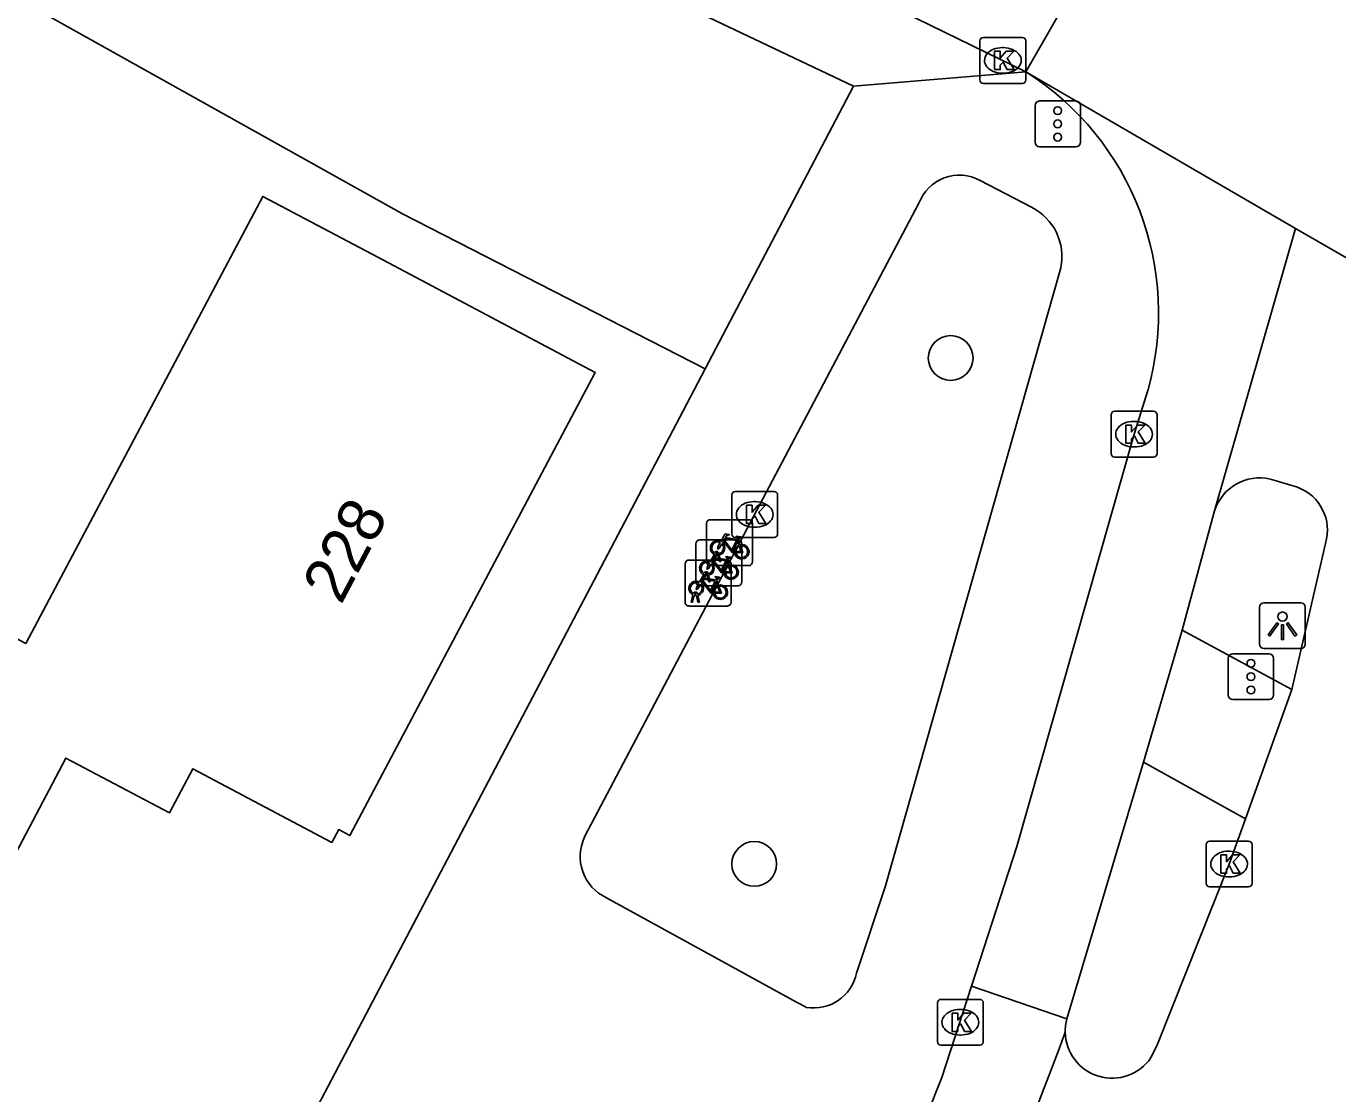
# Model space of a CAD drawing. Extents: x 160158 to 160921, y 381517 to 382041.
# Drawn here: x 160614.39 to 160643.01, y 381865.63 to 381888.94 of the extents above; entities that cross this region are included whole.
import ezdxf

# ---------------------------------------------------------------- set-up
doc = ezdxf.new("R2010")
doc.units = 0
for name, color, linetype in [('IMGEO_Boom', 7, 'Continuous'), ('IMGEO_Fietsenrek', 7, 'Continuous'), ('IMGEO_Fietspad_open', 7, 'Continuous'), ('IMGEO_Groenvoorziening', 7, 'Continuous'), ('IMGEO_Kolk', 7, 'Continuous'), ('IMGEO_Lichtpunt', 7, 'Continuous'), ('IMGEO_Pand', 7, 'Continuous'), ('IMGEO_Pand_nummerreeks', 7, 'Continuous'), ('IMGEO_Rijbaan_lokaal_open', 7, 'Continuous'), ('IMGEO_Rijbaan_regionaal_gesloten', 7, 'Continuous'), ('IMGEO_Verkeersregelinstallatiepaal', 7, 'Continuous'), ('IMGEO_Voetpad_open', 7, 'Continuous')]:
    doc.layers.add(name, color=color, linetype=linetype)

msp = doc.modelspace()

# ---------------------------------------------------------------- linework, layer by layer
at = {"layer": 'IMGEO_Boom'}
for centre in [(160634.563, 381881.7), (160630.276, 381870.653)]:
    msp.add_circle(centre, 0.489, dxfattribs=at)
at = {"layer": 'IMGEO_Fietsenrek'}
for p, q in [((160629.236, 381877.245), (160629.236, 381878.086)), ((160629.236, 381878.086), (160629.236, 381877.245)), ((160629.311, 381878.17), (160630.152, 381878.17)), ((160630.152, 381878.17), (160629.311, 381878.17)), ((160630.236, 381878.095), (160630.236, 381877.254)), ((160630.236, 381877.254), (160630.236, 381878.095)), ((160629.078, 381877.727), (160629.919, 381877.727)), ((160629.919, 381877.727), (160629.078, 381877.727)), ((160629.923, 381877.719), (160629.959, 381877.624)), ((160629.003, 381876.802), (160629.003, 381877.643)), ((160629.003, 381877.643), (160629.003, 381876.802)), ((160629.363, 381877.254), (160629.402, 381877.414)), ((160629.432, 381877.402), (160629.397, 381877.254)), ((160629.474, 381877.426), (160629.473, 381877.43)), ((160629.515, 381877.254), (160629.481, 381877.396)), ((160629.505, 381877.437), (160629.506, 381877.43)), ((160629.513, 381877.4), (160629.548, 381877.254)), ((160630.003, 381877.652), (160630.003, 381876.811)), ((160630.003, 381876.811), (160630.003, 381877.652)), ((160628.769, 381876.36), (160628.769, 381877.201)), ((160628.769, 381877.201), (160628.769, 381876.36)), ((160628.844, 381877.285), (160629.685, 381877.285)), ((160629.685, 381877.285), (160628.844, 381877.285)), ((160630.161, 381877.17), (160629.32, 381877.17)), ((160629.32, 381877.17), (160630.161, 381877.17)), ((160629.397, 381877.254), (160629.363, 381877.254)), ((160629.548, 381877.254), (160629.515, 381877.254)), ((160629.69, 381877.276), (160629.726, 381877.181)), ((160629.769, 381877.21), (160629.769, 381876.369)), ((160629.769, 381876.369), (160629.769, 381877.21)), ((160629.13, 381876.811), (160629.169, 381876.971)), ((160629.164, 381876.811), (160629.13, 381876.811)), ((160629.199, 381876.959), (160629.164, 381876.811)), ((160629.241, 381876.983), (160629.24, 381876.987)), ((160629.282, 381876.811), (160629.248, 381876.953)), ((160629.272, 381876.994), (160629.273, 381876.987)), ((160629.28, 381876.957), (160629.315, 381876.811)), ((160629.315, 381876.811), (160629.282, 381876.811)), ((160629.456, 381876.834), (160629.492, 381876.739)), ((160628.896, 381876.369), (160628.935, 381876.529)), ((160628.965, 381876.517), (160628.93, 381876.369)), ((160629.007, 381876.541), (160629.006, 381876.545)), ((160629.048, 381876.369), (160629.014, 381876.511)), ((160629.038, 381876.552), (160629.039, 381876.545)), ((160629.046, 381876.515), (160629.081, 381876.369)), ((160629.928, 381876.727), (160629.087, 381876.727)), ((160629.087, 381876.727), (160629.928, 381876.727)), ((160629.694, 381876.285), (160628.853, 381876.285)), ((160628.853, 381876.285), (160629.694, 381876.285)), ((160628.93, 381876.369), (160628.896, 381876.369)), ((160629.081, 381876.369), (160629.048, 381876.369))]:
    msp.add_line(p, q, dxfattribs=at)
for points in [[(160629.57, 381877.644), (160629.518, 381877.554), (160629.478, 381877.529), (160629.479, 381877.576), (160629.534, 381877.67)], [(160629.549, 381877.696), (160629.644, 381877.86), (160629.73, 381877.846), (160629.732, 381877.837), (160629.676, 381877.826), (160629.649, 381877.781), (160629.905, 381877.74)], [(160629.845, 381877.452), (160629.795, 381877.452), (160629.604, 381877.703), (160629.585, 381877.671)], [(160629.892, 381877.715), (160629.635, 381877.756), (160629.618, 381877.727), (160629.785, 381877.507), (160629.892, 381877.715)], [(160629.94, 381877.617), (160629.91, 381877.694), (160629.801, 381877.476), (160629.844, 381877.476)], [(160629.905, 381877.74), (160629.93, 381877.789), (160629.924, 381877.793), (160629.901, 381877.797), (160629.889, 381877.804), (160629.888, 381877.807), (160629.89, 381877.812), (160629.985, 381877.797), (160629.987, 381877.787), (160629.977, 381877.774), (160629.965, 381877.768), (160629.951, 381877.774), (160629.923, 381877.719)], [(160629.316, 381877.253), (160629.411, 381877.417), (160629.497, 381877.403), (160629.499, 381877.394), (160629.443, 381877.383), (160629.416, 381877.338), (160629.672, 381877.297)], [(160629.874, 381877.476), (160629.994, 381877.475), (160629.95, 381877.589)], [(160629.97, 381877.596), (160630.025, 381877.451), (160629.875, 381877.451)], [(160629.337, 381877.201), (160629.285, 381877.111), (160629.245, 381877.086), (160629.246, 381877.133), (160629.301, 381877.227)], [(160629.612, 381877.009), (160629.562, 381877.009), (160629.371, 381877.26), (160629.352, 381877.228)], [(160629.659, 381877.272), (160629.402, 381877.313), (160629.385, 381877.284), (160629.552, 381877.064), (160629.659, 381877.272)], [(160629.707, 381877.174), (160629.677, 381877.251), (160629.568, 381877.033), (160629.611, 381877.033)], [(160629.641, 381877.033), (160629.761, 381877.032), (160629.717, 381877.146)], [(160629.737, 381877.153), (160629.792, 381877.008), (160629.642, 381877.008)], [(160629.672, 381877.297), (160629.697, 381877.346), (160629.691, 381877.35), (160629.668, 381877.354), (160629.656, 381877.361), (160629.655, 381877.364), (160629.657, 381877.369), (160629.752, 381877.354), (160629.754, 381877.344), (160629.744, 381877.331), (160629.732, 381877.325), (160629.718, 381877.331), (160629.69, 381877.276)], [(160629.082, 381876.811), (160629.177, 381876.975), (160629.263, 381876.961), (160629.265, 381876.952), (160629.209, 381876.941), (160629.182, 381876.896), (160629.438, 381876.855)], [(160629.378, 381876.567), (160629.328, 381876.567), (160629.137, 381876.818), (160629.118, 381876.786)], [(160629.425, 381876.83), (160629.168, 381876.871), (160629.151, 381876.842), (160629.318, 381876.622), (160629.425, 381876.83)], [(160629.473, 381876.732), (160629.443, 381876.809), (160629.334, 381876.591), (160629.377, 381876.591)], [(160629.438, 381876.855), (160629.463, 381876.904), (160629.457, 381876.908), (160629.434, 381876.912), (160629.422, 381876.919), (160629.421, 381876.922), (160629.423, 381876.927), (160629.518, 381876.912), (160629.52, 381876.902), (160629.51, 381876.889), (160629.498, 381876.883), (160629.484, 381876.889), (160629.456, 381876.834)], [(160629.103, 381876.759), (160629.051, 381876.669), (160629.011, 381876.644), (160629.012, 381876.691), (160629.067, 381876.785)], [(160629.407, 381876.591), (160629.527, 381876.59), (160629.483, 381876.704)], [(160629.503, 381876.711), (160629.558, 381876.566), (160629.408, 381876.566)]]:
    msp.add_lwpolyline(points, dxfattribs=at)
for centre, radius, start, end in [((160629.314, 381878.092), 0.0779, 92.4484, 184.2845), ((160629.314, 381878.092), 0.0779, 92.4484, 184.2845), ((160630.158, 381878.092), 0.0779, 2.4484, 94.2845), ((160630.158, 381878.092), 0.0779, 2.4484, 94.2845), ((160629.081, 381877.649), 0.0779, 92.4484, 184.2845), ((160629.081, 381877.649), 0.0779, 92.4484, 184.2845), ((160629.476, 381877.555), 0.159, 62.6766, 242.1369), ((160629.476, 381877.555), 0.129, 63.3192, 238.903), ((160629.476, 381877.555), 0.159, 283.5766, 46.6042), ((160629.925, 381877.649), 0.0779, 2.4484, 94.2845), ((160629.925, 381877.649), 0.0779, 2.4484, 94.2845), ((160629.456, 381877.426), 0.0499, 12.8025, 158.6934), ((160629.476, 381877.555), 0.159, 253.9967, 271.7867), ((160629.456, 381877.426), 0.0174, 12.8025, 163.4502), ((160629.476, 381877.555), 0.129, 253.415, 269.0204), ((160629.476, 381877.555), 0.129, 283.6043, 43.4302), ((160630.003, 381877.471), 0.159, 113.3408, 178.3217), ((160630.003, 381877.471), 0.159, 187.0065, 105.7708), ((160630.003, 381877.471), 0.129, 113.923, 177.9556), ((160630.003, 381877.471), 0.129, 188.6715, 104.5883), ((160628.847, 381877.207), 0.0779, 92.4484, 184.2845), ((160628.847, 381877.207), 0.0779, 92.4484, 184.2845), ((160629.243, 381877.112), 0.159, 62.6766, 242.1369), ((160629.243, 381877.112), 0.129, 63.3192, 238.903), ((160629.314, 381877.248), 0.0779, 182.4484, 274.2845), ((160629.314, 381877.248), 0.0779, 182.4484, 274.2845), ((160629.243, 381877.112), 0.129, 283.6043, 43.4302), ((160629.243, 381877.112), 0.159, 283.5766, 46.6042), ((160629.77, 381877.028), 0.159, 113.3408, 178.3217), ((160629.77, 381877.028), 0.159, 187.0065, 105.7708), ((160629.77, 381877.028), 0.129, 113.923, 177.9556), ((160629.77, 381877.028), 0.129, 188.6715, 104.5883), ((160629.691, 381877.207), 0.0779, 2.4484, 94.2845), ((160629.691, 381877.207), 0.0779, 2.4484, 94.2845), ((160630.158, 381877.248), 0.0779, 272.4484, 4.2845), ((160630.158, 381877.248), 0.0779, 272.4484, 4.2845), ((160629.009, 381876.67), 0.159, 62.6766, 242.1369), ((160629.009, 381876.67), 0.129, 63.3192, 238.903), ((160629.081, 381876.805), 0.0779, 182.4484, 274.2845), ((160629.081, 381876.805), 0.0779, 182.4484, 274.2845), ((160629.223, 381876.983), 0.0499, 12.8025, 158.6934), ((160629.243, 381877.112), 0.159, 253.9967, 271.7867), ((160629.223, 381876.983), 0.0174, 12.8025, 163.4502), ((160629.243, 381877.112), 0.129, 253.415, 269.0204), ((160629.925, 381876.805), 0.0779, 272.4484, 4.2845), ((160629.925, 381876.805), 0.0779, 272.4484, 4.2845), ((160628.989, 381876.541), 0.0499, 12.8025, 158.6934), ((160629.009, 381876.67), 0.159, 253.9967, 271.7867), ((160628.989, 381876.541), 0.0174, 12.8025, 163.4502), ((160629.009, 381876.67), 0.129, 253.415, 269.0204), ((160629.009, 381876.67), 0.129, 283.6043, 43.4302), ((160629.009, 381876.67), 0.159, 283.5766, 46.6042), ((160629.536, 381876.586), 0.159, 113.3408, 178.3217), ((160629.536, 381876.586), 0.159, 187.0065, 105.7708), ((160629.536, 381876.586), 0.129, 113.923, 177.9556), ((160629.536, 381876.586), 0.129, 188.6715, 104.5883), ((160628.847, 381876.363), 0.0779, 182.4484, 274.2845), ((160628.847, 381876.363), 0.0779, 182.4484, 274.2845), ((160629.691, 381876.363), 0.0779, 272.4484, 4.2845), ((160629.691, 381876.363), 0.0779, 272.4484, 4.2845)]:
    msp.add_arc(centre, radius, start, end, dxfattribs=at)
at = {"layer": 'IMGEO_Fietspad_open'}
for points in [[(160635.017, 381867.981), (160636.009, 381871.036), (160638.567, 381880.037), (160638.867, 381880.987)], [(160639.619, 381875.761), (160640.325, 381878.361)], [(160638.771, 381872.873), (160639.619, 381875.761)], [(160637.101, 381867.271), (160638.771, 381872.873)]]:
    msp.add_lwpolyline(points, dxfattribs=at)
msp.add_arc((160632.856, 381882.68), 6.245, 344.2666, 57.5811, dxfattribs=at)
at = {"layer": 'IMGEO_Groenvoorziening'}
msp.add_lwpolyline([(160610.258, 381898.175), (160607.535, 381893.268), (160622.598, 381884.85), (160629.203, 381881.464)], dxfattribs=at)
at = {"layer": 'IMGEO_Kolk'}
for p, q in [((160635.202, 381887.771), (160635.202, 381888.623)), ((160635.277, 381888.697), (160636.129, 381888.697)), ((160636.203, 381888.623), (160636.203, 381887.771)), ((160635.69, 381888.477), (160635.715, 381888.477)), ((160636.129, 381887.697), (160635.277, 381887.697)), ((160635.713, 381887.917), (160635.688, 381887.917)), ((160638.141, 381880.537), (160638.993, 381880.537)), ((160638.066, 381879.611), (160638.066, 381880.463)), ((160638.554, 381880.317), (160638.579, 381880.317)), ((160639.067, 381880.463), (160639.067, 381879.611)), ((160638.577, 381879.757), (160638.552, 381879.757)), ((160638.993, 381879.537), (160638.141, 381879.537)), ((160629.785, 381877.858), (160629.785, 381878.71)), ((160629.86, 381878.784), (160630.712, 381878.784)), ((160630.273, 381878.564), (160630.298, 381878.564)), ((160630.786, 381878.71), (160630.786, 381877.858)), ((160630.296, 381878.004), (160630.271, 381878.004)), ((160630.712, 381877.784), (160629.86, 381877.784)), ((160640.14, 381870.225), (160640.14, 381871.077)), ((160640.215, 381871.151), (160641.067, 381871.151)), ((160641.141, 381871.077), (160641.141, 381870.225)), ((160640.628, 381870.931), (160640.653, 381870.931)), ((160640.651, 381870.371), (160640.626, 381870.371)), ((160641.067, 381870.151), (160640.215, 381870.151)), ((160634.349, 381867.696), (160635.201, 381867.696)), ((160634.274, 381866.77), (160634.274, 381867.622)), ((160634.762, 381867.476), (160634.787, 381867.476)), ((160635.275, 381867.622), (160635.275, 381866.77)), ((160634.785, 381866.916), (160634.76, 381866.916)), ((160635.201, 381866.696), (160634.349, 381866.696))]:
    msp.add_line(p, q, dxfattribs=at)
for points in [[(160635.202, 381887.771), (160635.202, 381888.623)], [(160635.277, 381888.697), (160636.129, 381888.697)], [(160636.203, 381888.623), (160636.203, 381887.771)], [(160635.523, 381888.397), (160635.646, 381888.397), (160635.646, 381888.246), (160635.776, 381888.397), (160635.94, 381888.397), (160635.794, 381888.246), (160635.947, 381887.997), (160635.795, 381887.997), (160635.71, 381888.161), (160635.646, 381888.094), (160635.646, 381887.997), (160635.523, 381887.997), (160635.523, 381888.397)], [(160636.129, 381887.697), (160635.277, 381887.697)], [(160638.141, 381880.537), (160638.993, 381880.537)], [(160638.066, 381879.611), (160638.066, 381880.463)], [(160638.387, 381880.237), (160638.51, 381880.237), (160638.51, 381880.086), (160638.64, 381880.237), (160638.804, 381880.237), (160638.658, 381880.086), (160638.811, 381879.837), (160638.659, 381879.837), (160638.574, 381880.001), (160638.51, 381879.934), (160638.51, 381879.837), (160638.387, 381879.837), (160638.387, 381880.237)], [(160639.067, 381880.463), (160639.067, 381879.611)], [(160638.993, 381879.537), (160638.141, 381879.537)], [(160629.785, 381877.858), (160629.785, 381878.71)], [(160629.86, 381878.784), (160630.712, 381878.784)], [(160630.786, 381878.71), (160630.786, 381877.858)], [(160630.106, 381878.484), (160630.229, 381878.484), (160630.229, 381878.333), (160630.359, 381878.484), (160630.523, 381878.484), (160630.377, 381878.333), (160630.53, 381878.084), (160630.378, 381878.084), (160630.293, 381878.248), (160630.229, 381878.181), (160630.229, 381878.084), (160630.106, 381878.084), (160630.106, 381878.484)], [(160630.712, 381877.784), (160629.86, 381877.784)], [(160640.14, 381870.225), (160640.14, 381871.077)], [(160640.215, 381871.151), (160641.067, 381871.151)], [(160641.141, 381871.077), (160641.141, 381870.225)], [(160640.461, 381870.851), (160640.584, 381870.851), (160640.584, 381870.7), (160640.714, 381870.851), (160640.878, 381870.851), (160640.732, 381870.7), (160640.885, 381870.451), (160640.733, 381870.451), (160640.648, 381870.615), (160640.584, 381870.548), (160640.584, 381870.451), (160640.461, 381870.451), (160640.461, 381870.851)], [(160641.067, 381870.151), (160640.215, 381870.151)], [(160634.349, 381867.696), (160635.201, 381867.696)], [(160634.274, 381866.77), (160634.274, 381867.622)], [(160634.595, 381867.396), (160634.718, 381867.396), (160634.718, 381867.245), (160634.848, 381867.396), (160635.012, 381867.396), (160634.866, 381867.245), (160635.019, 381866.996), (160634.867, 381866.996), (160634.782, 381867.16), (160634.718, 381867.093), (160634.718, 381866.996), (160634.595, 381866.996), (160634.595, 381867.396)], [(160635.275, 381867.622), (160635.275, 381866.77)], [(160635.201, 381866.696), (160634.349, 381866.696)]]:
    msp.add_lwpolyline(points, dxfattribs=at)
for centre, start, end in [((160635.279, 381888.621), 91.552, 178.448), ((160635.279, 381888.621), 91.552, 178.448), ((160636.127, 381888.621), 1.552, 88.448), ((160636.127, 381888.621), 1.552, 88.448), ((160635.279, 381887.773), 181.552, 268.448), ((160635.279, 381887.773), 181.552, 268.448), ((160636.127, 381887.773), 271.552, 358.448), ((160636.127, 381887.773), 271.552, 358.448), ((160638.143, 381880.461), 91.552, 178.448), ((160638.143, 381880.461), 91.552, 178.448), ((160638.991, 381880.461), 1.552, 88.448), ((160638.991, 381880.461), 1.552, 88.448), ((160638.143, 381879.613), 181.552, 268.448), ((160638.143, 381879.613), 181.552, 268.448), ((160638.991, 381879.613), 271.552, 358.448), ((160638.991, 381879.613), 271.552, 358.448), ((160629.862, 381878.708), 91.552, 178.448), ((160629.862, 381878.708), 91.552, 178.448), ((160630.71, 381878.708), 1.552, 88.448), ((160630.71, 381878.708), 1.552, 88.448), ((160629.862, 381877.86), 181.552, 268.448), ((160629.862, 381877.86), 181.552, 268.448), ((160630.71, 381877.86), 271.552, 358.448), ((160630.71, 381877.86), 271.552, 358.448), ((160640.217, 381871.075), 91.552, 178.448), ((160640.217, 381871.075), 91.552, 178.448), ((160641.065, 381871.075), 1.552, 88.448), ((160641.065, 381871.075), 1.552, 88.448), ((160640.217, 381870.227), 181.552, 268.448), ((160640.217, 381870.227), 181.552, 268.448), ((160641.065, 381870.227), 271.552, 358.448), ((160641.065, 381870.227), 271.552, 358.448), ((160634.351, 381867.62), 91.552, 178.448), ((160634.351, 381867.62), 91.552, 178.448), ((160635.199, 381867.62), 1.552, 88.448), ((160635.199, 381867.62), 1.552, 88.448), ((160634.351, 381866.772), 181.552, 268.448), ((160634.351, 381866.772), 181.552, 268.448), ((160635.199, 381866.772), 271.552, 358.448), ((160635.199, 381866.772), 271.552, 358.448)]:
    msp.add_arc(centre, 0.0765, start, end, dxfattribs=at)
for centre, major_axis, ratio, start_param, end_param in [((160635.689, 381888.197), (-0.387, 0.002), 0.722429, 4.712389, 7.853982), ((160635.714, 381888.197), (-0.39, 0.002), 0.717154, 1.570796, 4.712389), ((160638.553, 381880.037), (-0.387, 0.002), 0.722429, 4.712389, 7.853982), ((160638.578, 381880.037), (-0.39, 0.002), 0.717154, 1.570796, 4.712389), ((160630.272, 381878.284), (-0.387, 0.002), 0.722429, 4.712389, 7.853982), ((160630.297, 381878.284), (-0.39, 0.002), 0.717154, 1.570796, 4.712389), ((160640.627, 381870.651), (-0.387, 0.002), 0.722429, 4.712389, 7.853982), ((160640.652, 381870.651), (-0.39, 0.002), 0.717154, 1.570796, 4.712389), ((160634.761, 381867.196), (-0.387, 0.002), 0.722429, 4.712389, 7.853982), ((160634.786, 381867.196), (-0.39, 0.002), 0.717154, 1.570796, 4.712389)]:
    msp.add_ellipse(centre, major_axis=major_axis, ratio=ratio, start_param=start_param, end_param=end_param, dxfattribs=at)
at = {"layer": 'IMGEO_Lichtpunt'}
for p, q in [((160641.307, 381876.257), (160641.307, 381875.45)), ((160641.307, 381876.257), (160641.307, 381875.45)), ((160642.209, 381876.352), (160641.401, 381876.352)), ((160642.209, 381876.352), (160641.401, 381876.352)), ((160642.303, 381875.45), (160642.303, 381876.257)), ((160642.303, 381875.45), (160642.303, 381876.257)), ((160641.401, 381875.356), (160642.209, 381875.356)), ((160641.401, 381875.356), (160642.209, 381875.356))]:
    msp.add_line(p, q, dxfattribs=at)
for points in [[(160641.681, 381875.921), (160641.72, 381875.893), (160641.532, 381875.631), (160641.494, 381875.658), (160641.681, 381875.921)], [(160641.783, 381875.873), (160641.83, 381875.873), (160641.83, 381875.551), (160641.783, 381875.551), (160641.783, 381875.873)], [(160641.893, 381875.893), (160641.931, 381875.92), (160642.118, 381875.658), (160642.079, 381875.63), (160641.893, 381875.893)]]:
    msp.add_lwpolyline(points, dxfattribs=at)
msp.add_circle((160641.806, 381876.055), 0.0994, dxfattribs=at)
for centre, start, end in [((160641.401, 381876.257), 90, 180), ((160641.401, 381876.257), 90, 180), ((160642.209, 381876.257), 0, 90), ((160642.209, 381876.257), 0, 90), ((160641.401, 381875.45), 180, 270), ((160641.401, 381875.45), 180, 270), ((160642.209, 381875.45), 270, 0), ((160642.209, 381875.45), 270, 360)]:
    msp.add_arc(centre, 0.0946, start, end, dxfattribs=at)
at = {"layer": 'IMGEO_Pand'}
msp.add_lwpolyline([(160606.729, 381873.616), (160609.171, 381878.228), (160614.38, 381875.468), (160619.551, 381885.229), (160622.062, 381883.899), (160626.806, 381881.386), (160621.45, 381871.274), (160621.206, 381871.403), (160621.057, 381871.123), (160618.022, 381872.731), (160617.512, 381871.77), (160615.253, 381872.966), (160613.654, 381869.948), (160606.729, 381873.616)], dxfattribs=at)
at = {"layer": 'IMGEO_Rijbaan_lokaal_open'}
for points in [[(160636.204, 381887.952), (160611.521, 381899.997), (160603.437, 381903.912), (160575.677, 381917.504)], [(160638.836, 381892.54), (160636.204, 381887.952)], [(160636.204, 381887.952), (160642.093, 381884.528)], [(160642.093, 381884.528), (160640.325, 381878.361)], [(160655.242, 381876.949), (160642.093, 381884.528)], [(160641.541, 381879.058), (160642.134, 381878.878)], [(160642.747, 381877.653), (160642.011, 381874.463)], [(160642.011, 381874.463), (160640.999, 381871.637)], [(160640.999, 381871.637), (160640.641, 381870.651), (160639.061, 381866.68), (160638.935, 381866.423)], [(160629.976, 381855.653), (160631.978, 381859.981), (160634.372, 381865.993), (160635.017, 381867.981)], [(160637.101, 381867.271), (160635.017, 381867.981)]]:
    msp.add_lwpolyline(points, dxfattribs=at)
for centre, radius, start, end in [((160641.307, 381878.056), 1.028, 76.8694, 162.7725), ((160641.784, 381877.937), 1.004, 343.5659, 69.6017), ((160638.07, 381867), 1.006, 164.3766, 181.0318), ((160505.827, 381915.432), 139.895, 331.19852, 339.7369), ((160638.088, 381866.998), 1.024, 180.8717, 325.8591)]:
    msp.add_arc(centre, radius, start, end, dxfattribs=at)
at = {"layer": 'IMGEO_Rijbaan_regionaal_gesloten'}
msp.add_arc((160802.115, 382215.631), 358.371, 243.56615, 246.89778, dxfattribs=at)
at = {"layer": 'IMGEO_Verkeersregelinstallatiepaal'}
for p, q in [((160636.405, 381886.412), (160636.405, 381887.212)), ((160636.405, 381887.212), (160636.405, 381886.412)), ((160636.505, 381887.312), (160637.295, 381887.312)), ((160637.295, 381887.312), (160636.505, 381887.312)), ((160637.395, 381887.212), (160637.395, 381886.412)), ((160637.395, 381886.412), (160637.395, 381887.212)), ((160637.295, 381886.312), (160636.505, 381886.312)), ((160636.505, 381886.312), (160637.295, 381886.312)), ((160640.622, 381874.342), (160640.622, 381875.142)), ((160640.622, 381875.142), (160640.622, 381874.342)), ((160640.722, 381875.242), (160641.512, 381875.242)), ((160641.512, 381875.242), (160640.722, 381875.242)), ((160641.612, 381875.142), (160641.612, 381874.342)), ((160641.612, 381874.342), (160641.612, 381875.142)), ((160641.512, 381874.242), (160640.722, 381874.242)), ((160640.722, 381874.242), (160641.512, 381874.242))]:
    msp.add_line(p, q, dxfattribs=at)
for centre in [(160636.9, 381887.102), (160636.9, 381886.812), (160636.9, 381886.522), (160641.117, 381875.032), (160641.117, 381874.742), (160641.117, 381874.452)]:
    msp.add_circle(centre, 0.085, dxfattribs=at)
for centre, start, end in [((160636.505, 381887.212), 90, 180), ((160636.505, 381887.212), 90, 180), ((160637.295, 381887.212), 0, 90), ((160637.295, 381887.212), 360, 90), ((160636.505, 381886.412), 180, 270), ((160636.505, 381886.412), 180, 270), ((160637.295, 381886.412), 270, 0), ((160637.295, 381886.412), 270, 0), ((160640.722, 381875.142), 90, 180), ((160640.722, 381875.142), 90, 180), ((160641.512, 381875.142), 0, 90), ((160641.512, 381875.142), 360, 90), ((160640.722, 381874.342), 180, 270), ((160640.722, 381874.342), 180, 270), ((160641.512, 381874.342), 270, 0), ((160641.512, 381874.342), 270, 0)]:
    msp.add_arc(centre, 0.1, start, end, dxfattribs=at)
at = {"layer": 'IMGEO_Voetpad_open'}
for points in [[(160632.445, 381887.634), (160610.579, 381898.023), (160610.258, 381898.175)], [(160636.204, 381887.952), (160632.445, 381887.634)], [(160629.203, 381881.464), (160632.445, 381887.634)], [(160635.207, 381885.579), (160636.329, 381884.992)], [(160626.581, 381871.257), (160633.87, 381885.078)], [(160636.965, 381883.668), (160633.138, 381870.174), (160632.507, 381868.27)], [(160629.203, 381881.464), (160628.641, 381880.394), (160617.475, 381859.142)], [(160639.619, 381875.761), (160642.011, 381874.463)], [(160640.999, 381871.637), (160638.771, 381872.873)], [(160631.41, 381867.522), (160631.195, 381867.633), (160627.049, 381869.914)]]:
    msp.add_lwpolyline(points, dxfattribs=at)
for centre, radius, start, end in [((160634.755, 381884.75), 0.944, 61.4207, 159.6632), ((160635.791, 381883.919), 1.2, 347.9326, 63.3832), ((160627.473, 381870.815), 0.996, 153.6412, 244.7829), ((160631.572, 381868.462), 0.954, 260.2076, 348.3694)]:
    msp.add_arc(centre, radius, start, end, dxfattribs=at)

# ---------------------------------------------------------------- texts
at = {"layer": 'IMGEO_Pand_nummerreeks'}
msp.add_text('228', height=1, rotation=62.0913, dxfattribs=at).set_placement((160621.257, 381876.293))

doc.saveas('drawing.dxf')
